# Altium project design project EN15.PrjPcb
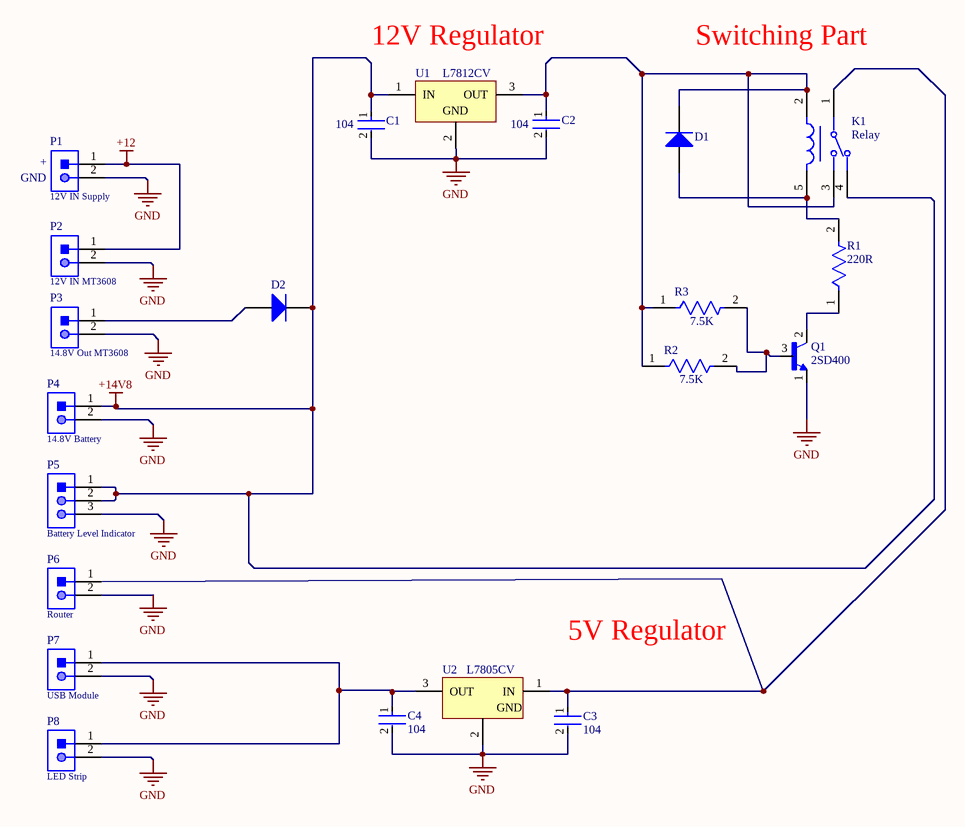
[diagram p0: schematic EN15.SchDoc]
1 sheet, 21 parts. Net scope: global (net labels, ports and power ports of the same name join across sheets).
Board file: PCB EN 15.PcbDoc

## Sheet schematic EN15.SchDoc
size A; Author: Dojitha Mirihagalla; DrawnBy: Dojitha Mirihagalla; SheetNumber: 1; SheetTotal: 1; SPICEModelCacheLWYSPOIM: <root> / <DocumentId>LWYSPOIM</DocumentId> / <CacheFrame Number="0"> / <Model Name="1n4001" Kind="MDL"> / <Text>*1N4001 MCE 8-16-95 / *50V 1A Si GenPurpose Diode pkg:DIODE0.4 1,2 / .MODEL 1N4001 D(IS=2.55E-9 RS=0.042 N=1.75 TT=5.76E-6 CJO=1.85E-11 / + VJ=0.75 M=0.333 BV=50 IBV=1E-5 )</Text> / </Model> / </CacheFrame> / </root>

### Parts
C1  104  [FP-RCE0K1-MFG]
C2  104  [FP-RCE0K1-MFG]
C3  104  [FP-RCE0K1-MFG]
C4  104  [FP-RCE0K1-MFG]
D1  Diode 1N4001  [DO-41]  (value not drawn)
D2  Diode 1N4001  [DO-41]  (value not drawn)
K1  Relay  [FP-JS1-5V-F-MFG]
P1  12V IN Supply  [61300211121]
P2  12V IN MT3608  [61300211121]
P3  14.8V Out MT3608  [61300211121]
P4  14.8V Battery  [61300211121]
P5  Battery Level Indicator  [61900319521]
P6  Router  [61300211121]
P7  USB Module  [61300211121]
P8  LED Strip  [61300211121]
Q1  2SD400  [TO145P470X600X850-3P]
R1  Resistance: 220R  [FP-CF14-MFG]  (hidden comment: PCF14JT7K50)
R2  Resistance: 7.5K  [FP-CF14-MFG]  (hidden comment: PCF14JT7K50)
R3  Resistance: 7.5K  [FP-CF14-MFG]  (hidden comment: PCF14JT7K50)
U1  L7812CV  [TO220]
U2  L7805CV  [TO220]

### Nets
+12: P1.1 P2.1
+14V8: C1.1 D2.2(K) K1.4(N.C.) P4.1 P5.1 P5.2 U1.1(IN)
GND: C1.2 C2.2 C3.2 C4.2 P1.2 P2.2 P3.2 P4.2 P5.3 P6.2 P7.2 P8.2 Q1.1(E) U1.2(GND) U2.2(GND)
NetC2_1: C2.1 D1.2(K) K1.2(1_COIL) K1.3(N.O.) R2.1 R3.1 U1.3(OUT)
NetC3_1: C3.1 K1.1(COM) P6.1 U2.1(IN)
NetC4_1: C4.1 P7.1 P8.1 U2.3(OUT)
NetD1_1: D1.1(A) K1.5(2_COIL) R1.2
NetD2_1: D2.1(A) P3.1
NetQ1_2: Q1.2(C) R1.1
NetQ1_3: Q1.3(B) R2.2 R3.2

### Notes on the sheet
- (near U1) 12V Regulator
- Switching Part
- (near P1) +
- (near P1) GND
- 5V Regulator

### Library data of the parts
C1-C4 = CMP-06035-043061-1: Cap Ceramic 1pF 100V C0G ±0.25pF Radial 5mm +125°C Automotive Bulk; Lead Diameter: 0.5mm; Lead/Base Style: Formed Leads
D1 D2 = Diode 1N4001: 1 Amp General Purpose Rectifier
K1 = CMP-05606-000016-1: RELAY GEN PURPOSE SPDT 10A 5V; Manufacturer Part Number: JS1-5V-F; Manufacturer: Panasonic; Coil Type: Non-Latching; Number Of Contacts: 1; Standoff Height: 0.3mm; Switching Power: 150W; Coil Power: 360mW; Coil Current: 72mA; Coil Resistance: 69.4Ω
P1-P4 P6-P8 = CMP-1712-00002-4: THT Vertical Pin Header WR-PHD, Pitch 2.54 mm, Single Row, 2 pins; Manufacturer: Wurth Elektronik; Rated Current: 3A; Gender: Male; Withstanding Voltage: 500VAC; Working Voltage: 250VAC; Pitch: 2.54mm; Contact Resistance: 20mOhm; Pin Number: 2
P5 = CMP-1502-00600-1: Male Top Locking Header WR-WTB, THT, Right Angled, pitch 2.54 mm, 1 x 3 position; Manufacturer: Wurth Elektronik; Working Voltage: 250VAC; Pitch: 2.54mm; Position: 1x3; Contact Resistance: 20mOhm
Q1 = 2SD400: Connector Header Through Hole 20 position 0.100 _2.54mm_; MF: Samtec Inc.
R1-R3 = CMP-26528-000003-1: RES 7.5K OHM 1/4W 5% AXIAL; Max Power Dissipation: 250mW; Temperature Coefficient: -400ppm/°C
U1 = CMP-0244-00450-1: Positive Voltage Regulator, 12V, 3-Pin TO-220
U2 = CMP-0244-00483-1: Positive Voltage Regulator, 5V, 3-Pin TO-220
